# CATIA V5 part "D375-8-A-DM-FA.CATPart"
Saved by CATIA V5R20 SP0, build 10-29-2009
Part number: D375-8-A-DM-FA
Bounding box of the stored display mesh (mm): x -10 to 0, y -4 to 4, z -4 to 4
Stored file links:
  C:\Users\Utente\Desktop\IO LAVORO\3D X SITO CF\X SITO\PLASTICA\D375\D375-8-A-DM-FA.CATPart
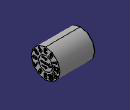
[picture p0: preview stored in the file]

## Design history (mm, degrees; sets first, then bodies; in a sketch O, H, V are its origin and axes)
Set1
  DatumSurface1 to DatumSurface216 "D375-8-A-DM-FA"
Body1 (main body)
